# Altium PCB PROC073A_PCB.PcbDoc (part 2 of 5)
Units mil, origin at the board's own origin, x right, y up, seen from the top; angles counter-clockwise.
Board outline 2165.35 x 2165.35 mil, 6 copper layers (Top Layer, L2, L3, L4, L5, Bottom Layer), stack 55.77 mil thick; 284 components, 233 nets, 945 pads, 1419 vias.
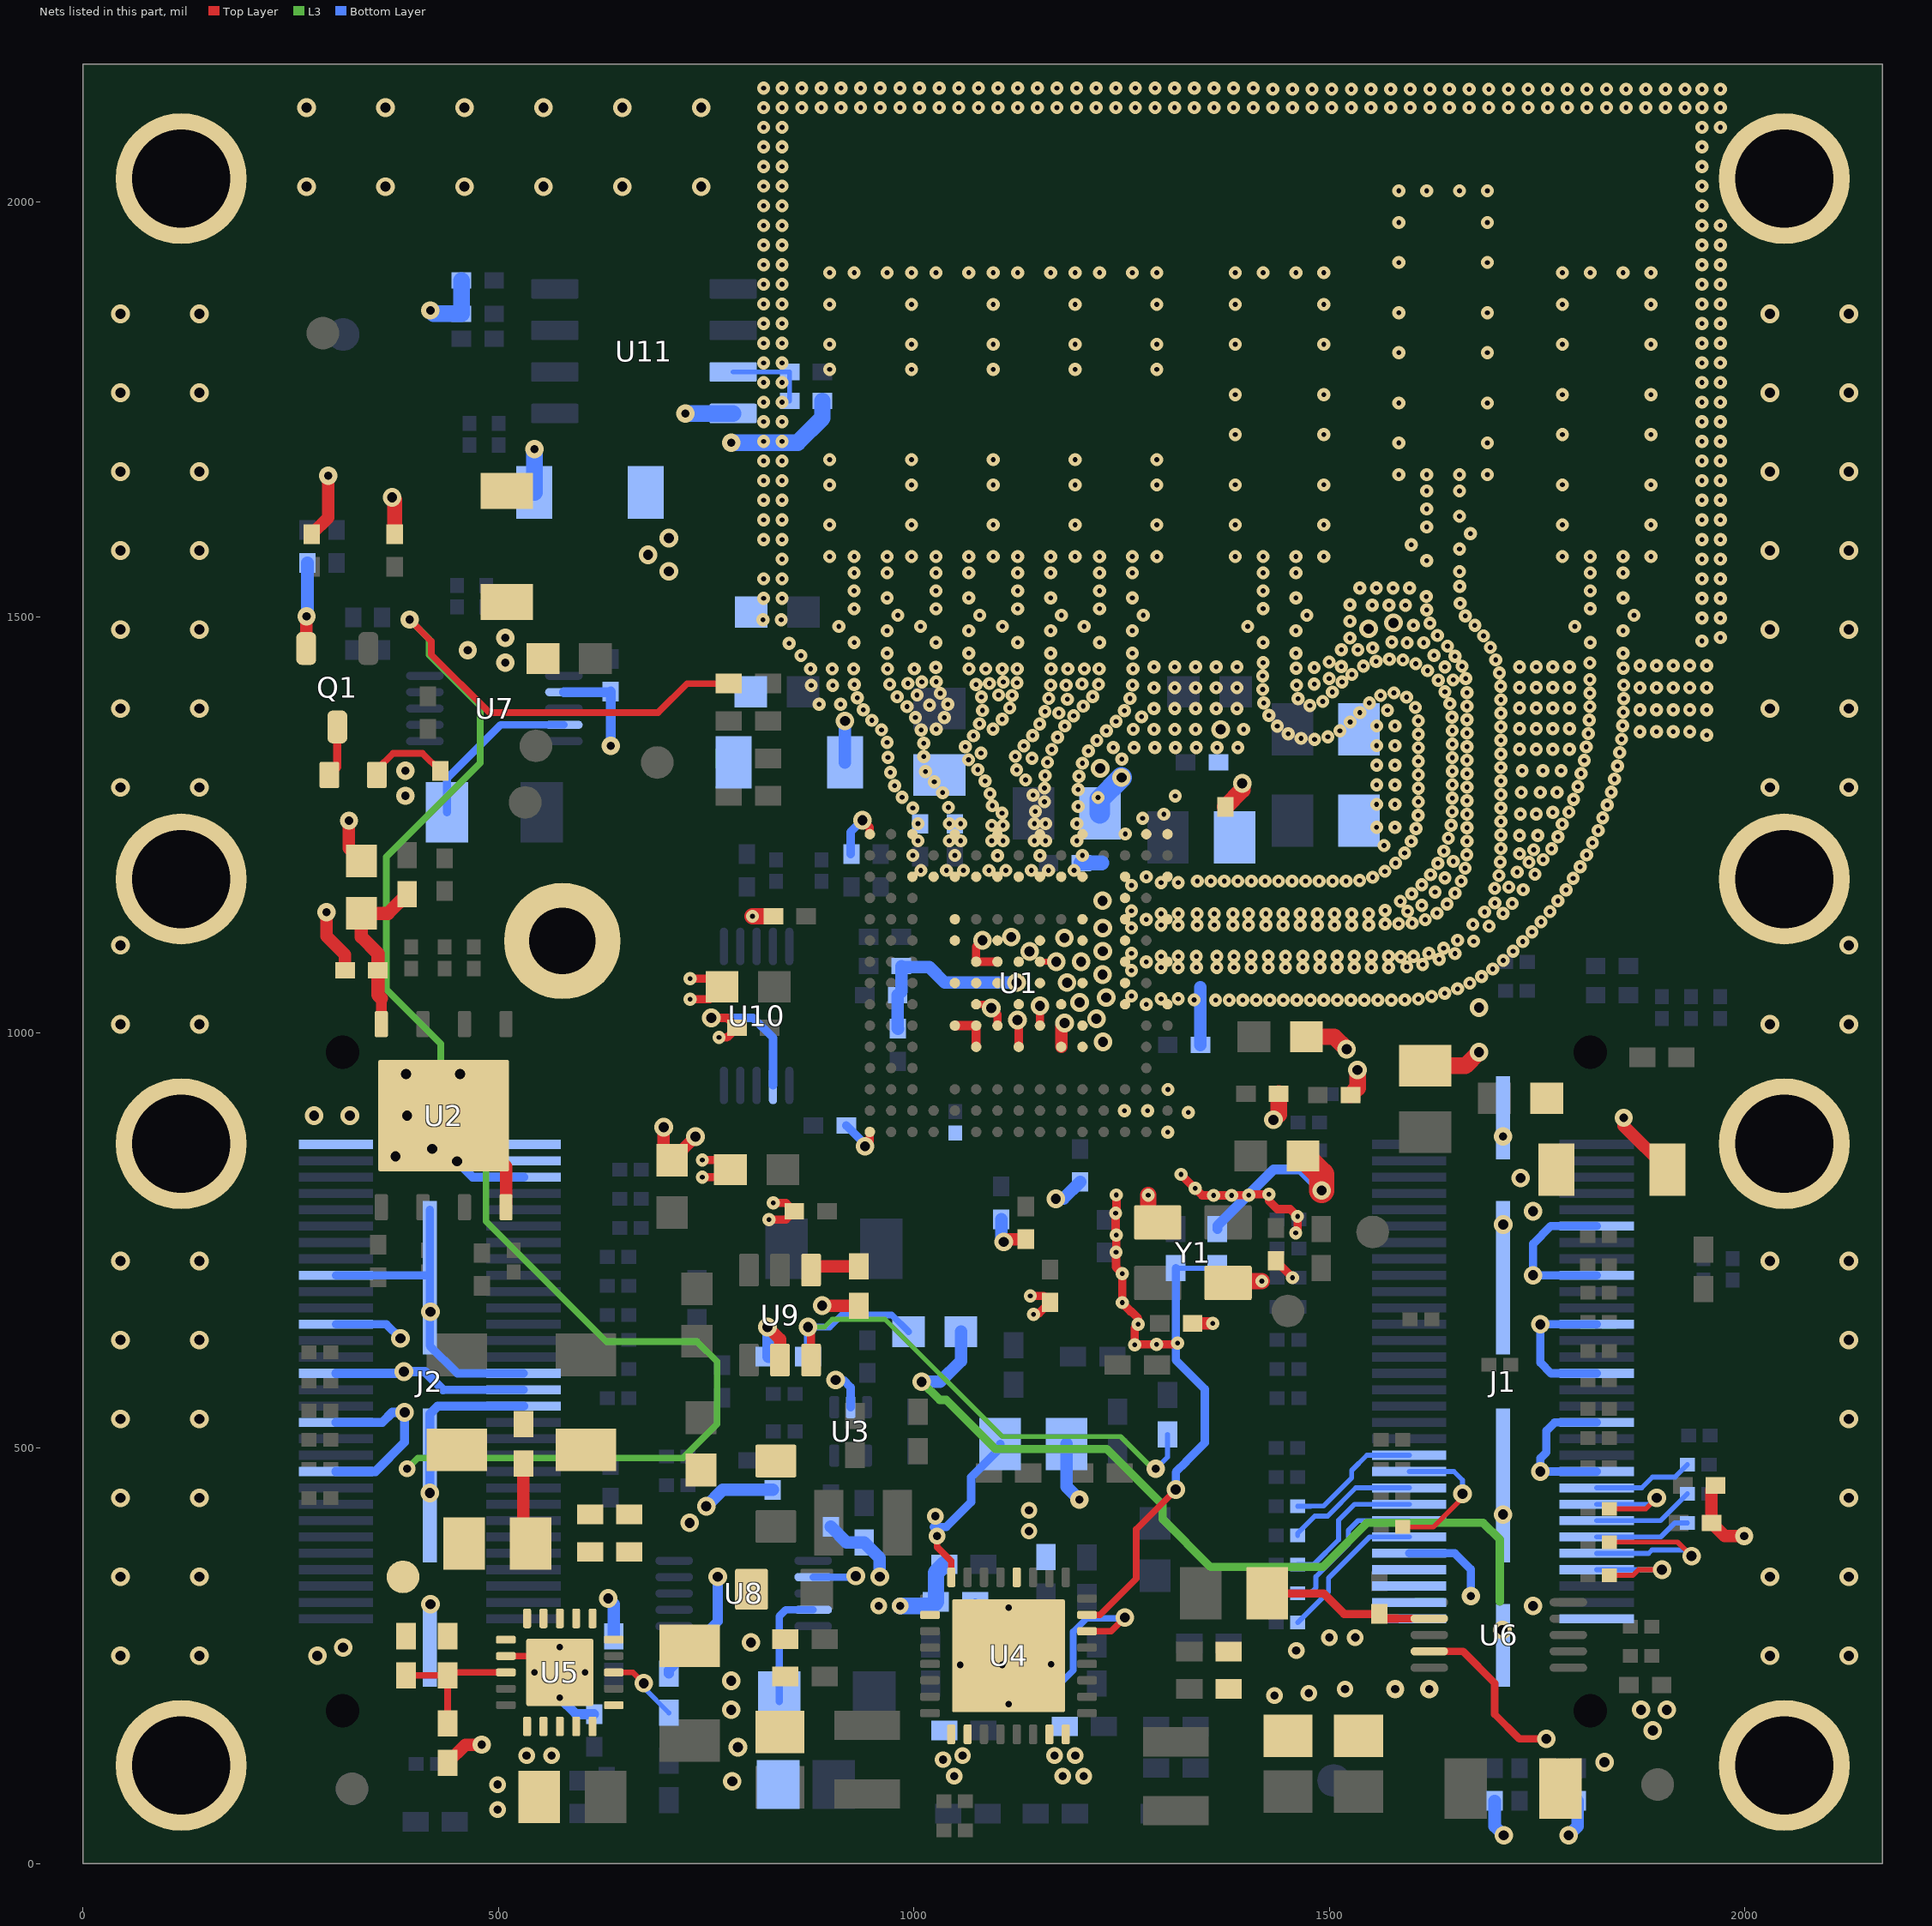
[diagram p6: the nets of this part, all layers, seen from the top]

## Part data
C1 C2 C3 C64: library part CMP-0008770-2, "CAP, CERM, 22 uF, 6.3 V, +/- 10%, X7R, AEC-Q200 Grade 1, 1206", Cap_Case=1206_180, Manufacturer=TDK, Supplier Part Number 1=445-7884-1-ND, TempCo=X7R, Tolerance_%=10%, Value1="0.001872 ohm", Value2=6.3V, ValueDisplayed=22uF
C4 C5 C6 C9 C10 C11 C12 C14 C16 C19 C20 C21 C28 C29: library part CMP-0078265-1, "CAP, CERM, 0.22 µF, 16 V,+/- 10%, X7R, AEC-Q200 Grade 1, 0402", Cap_Case=0402, Manufacturer=MuRata, Supplier Part Number 1=490-10671-1-ND, TempCo=X7R, Tolerance_%=10%, Value2=16V, ValueDisplayed=0.22µF
C7 C8 C13 C15 C23 C24 C45: library part CMP-0008017-2, "CAP, CERM, 10 uF, 10 V, +/- 10%, X7R, 0805", Cap_Case=0805, Manufacturer=MuRata, Supplier Part Number 1=490-10674-1-ND, TempCo=X7R, Tolerance_%=10%, Value1=Unknown, Value2=10V, ValueDisplayed=10uF
C17 C27: library part CMP-0007134-5, "CAP, CERM, 2.2 uF, 6.3 V, +/- 10%, X7R, AEC-Q200 Grade 1, 0603", Cap_Case=0603, Manufacturer=MuRata, Supplier Part Number 1=490-5316-1-ND, TempCo=X7R, Tolerance_%=10%, Value1=Unknown, Value2=6.3V, ValueDisplayed=2.2uF
C18 C22 C35: library part CMP-0007136-5, "CAP, CERM, 1 uF, 16 V, +/- 10%, X7R, AEC-Q200 Grade 1, 0603", Cap_Case=0603, Manufacturer=MuRata, Supplier Part Number 1=490-5241-6-ND, TempCo=X7R, Tolerance_%=10%, Value1=Unknown, Value2=16V, ValueDisplayed=1uF
C25 C26: library part CMP-0006351-2, "CAP, CERM, 0.1 uF, 16 V, +/- 10%, X7R, 0402", Cap_Case=0402, Manufacturer=MuRata, Supplier Part Number 1=490-4759-2-ND, TempCo=X7R, Tolerance_%=10%, Value1=Unknown, Value2=16V, ValueDisplayed=0.1uF
C30: library part CMP-0006352-2, "CAP, CERM, 0.01 uF, 25 V, +/- 10%, X7R, 0402", Cap_Case=0402, Manufacturer=MuRata, Supplier Part Number 1=490-6043-2-ND, TempCo=X7R, Tolerance_%=10%, Value1=Unknown, Value2=25V, ValueDisplayed=0.01uF
C31: library part CMP-0078219-1, "CAP, CERM, 0.1 µF, 10 V,+/- 10%, X7S, 0201", Cap_Case=0201, Manufacturer=TDK, Supplier Part Number 1=445-9051-1-ND, TempCo=X7S, Tolerance_%=10%, Value2=10V, ValueDisplayed=0.1µF
C32 C33: library part CMP-0006367-2, "CAP, CERM, 4.7 pF, 50 V, +/- 2%, C0G/NP0, 0402", Cap_Case=0402, Manufacturer=MuRata, Supplier Part Number 1=490-8102-1-ND, TempCo=C0G/NP0, Tolerance_%=2%, Value1=Unknown, Value2=50V, ValueDisplayed=4.7pF
C34 C36 C57 C58 C59 C63 C65: library part CMP-0006325-2, "CAP, CERM, 0.1 uF, 50 V, +/- 10%, X7R, AEC-Q200 Grade 1, 0402", Cap_Case=0402, Manufacturer=TDK, Supplier Part Number 1=445-6899-1-ND, TempCo=X7R, Tolerance_%=10%, Value1="0.039064 ohm", Value2=50V, ValueDisplayed=0.1uF
C37 C42 C49: library part CMP-0007995-2, "CAP, CERM, 10 uF, 16 V, +/- 10%, X7R, 0805", Cap_Case=0805, Manufacturer="Samsung Electro-Mechanics", TempCo=X7R, Tolerance_%=10%, Value1=Unknown, Value2=16V, ValueDisplayed=10uF
C38 C39 C43 C53 C62 C66 C67: library part CMP-0006201-2, "CAP, CERM, 0.1 uF, 16 V, +/- 10%, X7R, 0402", Cap_Case=0402, Manufacturer=AVX, Supplier Part Number 1=478-7888-1-ND, TempCo=X7R, Tolerance_%=10%, Value1=Unknown, Value2=16V, ValueDisplayed=0.1uF
C40 C41 C44 C46 C47: library part CMP-0008015-1, "CAP, CERM, 22 uF, 6.3 V, +/- 20%, X7T, AEC-Q200 Grade 1, 0805", Cap_Case=0805, Manufacturer=MuRata, TempCo=X7T, Tolerance_%=20%, Value1=Unknown, Value2=6.3V, ValueDisplayed=22uF
C48 C52: library part CMP-0006639-2, "CAP, CERM, 0.01 uF, 16 V, +/- 10%, X7R, 0402", Cap_Case=0402, Manufacturer=MuRata, Supplier Part Number 1=490-1313-1-ND, TempCo=X7R, Tolerance_%=10%, Value1=Unknown, Value2=16V, ValueDisplayed=0.01uF
C50: library part CMP-0007111-4, "CAP, CERM, 1 uF, 6.3 V, +/- 10%, X7R, 0603", Cap_Case=0603, Manufacturer="Samsung Electro-Mechanics", TempCo=X7R, Tolerance_%=10%, Value1=Unknown, Value2=6.3V, ValueDisplayed=1uF
C51: library part CMP-0007359-4, "CAP, CERM, 0.1 uF, 6.3 V, +/- 10%, X7R, 0603", Cap_Case=0603, Manufacturer=MuRata, Supplier Part Number 1=GRM188R70J104KA01D-ND, TempCo=X7R, Tolerance_%=10%, Value1=Unknown, Value2=6.3V, ValueDisplayed=0.1uF
C54 C55 C56: library part CMP-0081763-1, "CAP, CERM, 1 µF, 6.3 V,+/- 10%, X6S, 0402", Cap_Case=0402, Manufacturer=TDK, Supplier Part Number 1=445-13189-1-ND, TempCo=X6S, Tolerance_%=10%, Value2=6.3V, ValueDisplayed=1µF
C60: library part CMP-0006332-2, "CAP, CERM, 1000 pF, 100 V, +/- 10%, X7S, AEC-Q200 Grade 1, 0402", Cap_Case=0402, Manufacturer=TDK, Supplier Part Number 1=445-6904-1-ND, TempCo=X7S, Tolerance_%=10%, Value1="2.71151 ohm", Value2=100V, ValueDisplayed=1000pF
C61: library part CMP-0008203-2, "CAP, CERM, 22 uF, 16 V, +/- 20%, X5R, 0805", Cap_Case=0805, Manufacturer=MuRata, Supplier Part Number 1=490-9952-1-ND, TempCo=X5R, Tolerance_%=20%, Value1=Unknown, Value2=16V, ValueDisplayed=22uF
"CAUTION HOT SURFACE1": library part CMP-0074837-1, "IEC 61010-1 Hot Surface Warning"
DS1: library part CMP-0078196-1, "LED, Yellow, SMD", Color=yellow, Manufacturer=Vishay-Semiconductor, Power_TotalModule=40mW, Supplier Part Number 1=TLMY1000-GS08CT-ND, Value1=.04W, Value2=1.8V
FID1 FID2 FID3 FID4 FID5 FID6: library part CMP-0077181-1, "Fiducial mark.  There is nothing to buy or mount.", Manufacturer=N/A
J1 J2: library part CMP-0075524-1, "Receptacle, 0.5 mm, 30x2, Gold, TH", Color=Black, Manufacturer=Samtec, Supplier Part Number 1=SAM8180-ND
L1 L2 L3 L7: library part CMP-0077879-2, "Ferrite Bead, 120 ohm @ 100 MHz, 1.9 A, 0603", Manufacturer=MuRata, Supplier Part Number 1=490-13261-1-ND, Value1="0.04 ohm", Value2=1.9A, ValueDisplayed="120 ohm"
L4 L5: library part CMP-0058944-1, "Inductor, Shielded, 470 nH, 4.7 A, 0.021 ohm, SMD", Manufacturer="MuRata Toko", Value1="0.021 ohm", Value2=4.7A, ValueDisplayed=470nH
L6: library part CMP-0058938-1, "Inductor, Shielded, 1 uH, 3.8 A, 0.035 ohm, AEC-Q200 Grade 1, SMD", Manufacturer="MuRata Toko", Value1="0.035 ohm", Value2=3.8A, ValueDisplayed=1uH
LBL1: library part CMP-0003625-1, "Thermal Transfer Printable Labels, 0.650\" W x 0.200\" H - 10,000 per roll", Manufacturer=Brady, Supplier Part Number 1=97C5133
Logo1 Logo5: library part CMP-0074838-1, "Texas Instrument Corporate Signature"
Logo2: library part CMP-0074844-1
LOGO3: library part CMP-0074847-1, "FCC_disclaimer"
Logo4: library part CMP-0074769-1
Q1: library part CMP-0000947-2, "MOSFET, N-CH, 100 V, 0.17 A, SOT-23", Alternate Manufacturer=None, Manufacturer="Fairchild Semiconductor", Supplier Part Number 1=BSS123NCT-ND, Value1=1, Value2="1.8 nC"
R1 R99: library part CMP-0025884-3, "RES, 0, 5%, 0.125 W, 0603", Manufacturer=Vishay/Beyschlag, Power_W=125mW, Supplier Part Number 1=MCT0603-0.0-ZZCT-ND, TempCo=ppm/C, Tolerance_%=5%, Value2=0.125W, Value_Code=0000, ValueDisplayed=0
R2 R14 R44 R49 R52 R53 R54 R94 R101 R103 R104 R105 R106 R107 R112 R113 R114 R115 R116 R117 R139 R142 R145 R146 R147 R152 R157 R158 R161 R162: library part CMP-0025958-2, "RES, 10.0 k, 1%, 0.063 W, 0402", Manufacturer=Vishay-Dale, Power_W=63mW, Supplier Part Number 1=541-10.0KLCT-ND, TempCo="100 ppm/C", Tolerance_%=1%, Value2=0.063W, Value_Code=10k0, ValueDisplayed=10.0k
R3 R68 R70 R71 R81 R96 R123: library part CMP-0081623-1, "RES, 0.002, 1%, 1 W, AEC-Q200 Grade 0, 1206", Manufacturer=Rohm, Power_W=1W, Supplier Part Number 1=RHM.002ALCT-ND, TempCo="100 ppm/C", Tolerance_%=1%, Value_Code=2L000, ValueDisplayed=0.002
R4 R5 R6 R7 R8 R9 R10 R11 R12 R13 R16 R22 R24 R30 R31 R32 R33 R34 R35 R36 R37 R38 R39 R40 R41 R42 R58 R59 R60 R61 R62 R63 R64 R65 R66 R67 R131 R133 R134 R135 R136 R137 R140: library part CMP-0027008-3, "RES, 0, 5%, 0.05 W, 0201", Manufacturer=Vishay-Dale, Power_W=50mW, Supplier Part Number 1=72M6743, TempCo=ppm/C, Tolerance_%=5%, Value2=0.05W, Value_Code=0000, ValueDisplayed=0
R15 R17 R18 R19 R20 R21 R23 R26 R27 R28 R124 R125 R126 R127 R128 R129 R130 R132: library part CMP-0078192-1, "RES, 20.0, 1%, 0.05 W, 0201", Manufacturer=Vishay-Dale, Power_W=50mW, Supplier Part Number 1=541-2947-1-ND, TempCo="200 ppm/C", Tolerance_%=1%, Value2=0.05W, Value_Code=20R0, ValueDisplayed=20.0
R25 R29 R55 R56 R88 R89 R108 R109 R110 R111 R143 R144 R149 R159 R160: library part CMP-0027008-4, "RES, 0, 5%, 0.05 W, 0201", Manufacturer=Vishay-Dale, Power_W=50mW, Supplier Part Number 1=72M6743, TempCo=ppm/C, Tolerance_%=5%, Value2=0.05W, Value_Code=0000, ValueDisplayed=0
R43 R72 R73 R74 R75 R76 R77: library part CMP-0026992-3, "RES, 0, 5%, 0.1 W, AEC-Q200 Grade 0, 0402", Manufacturer=Panasonic, Power_W=100mW, Supplier Part Number 1=P0.0JCT-ND, TempCo="600 ppm/C", Tolerance_%=5%, Value2=0.1W, Value_Code=0000, ValueDisplayed=0
R45 R46 R47 R48 R51: library part CMP-0027275-2, "RES, 33.2, 1%, 0.05 W, 0201", Manufacturer=Vishay-Dale, Power_W=50mW, Supplier Part Number 1=541-33.2ABCT-ND, TempCo="200 ppm/C", Tolerance_%=1%, Value2=0.05W, Value_Code=33R2, ValueDisplayed=33.2
R50: library part CMP-0026395-1, "RES, 47.5 k, 1%, 0.063 W, 0402", Manufacturer=Vishay-Dale, Power_W=63mW, Supplier Part Number 1=541-47.5KLCT-ND, TempCo="100 ppm/C", Tolerance_%=1%, Value2=0.063W, Value_Code=47k5, ValueDisplayed=47.5k
R57 R69 R82 R83 R84 R90 R91 R93 R98 R102 R121 R151 R165 R166 R167 R168 R171: library part CMP-0026822-3, "RES, 0, 5%, 0.063 W, AEC-Q200 Grade 0, 0402", Manufacturer=Vishay-Dale, Power_W=63mW, Supplier Part Number 1=541-0.0JCT-ND, TempCo="200 ppm/C", Tolerance_%=5%, Value2=0.063W, Value_Code=0000, ValueDisplayed=0
R78 R79: library part CMP-0078212-1, "RES, 510, 5%, 0.1 W, AEC-Q200 Grade 0, 0402", Manufacturer=Panasonic, Power_W=100mW, Supplier Part Number 1=P510JCT-ND, TempCo="200 ppm/C", Tolerance_%=5%, Value2=0.1W, Value_Code=510R, ValueDisplayed=510
R80 R153 R154 R155 R156: library part CMP-0025950-2, "RES, 100 k, 1%, 0.063 W, 0402", Manufacturer=Vishay-Dale, Power_W=63mW, Supplier Part Number 1=541-100KLCT-ND, TempCo="100 ppm/C", Tolerance_%=1%, Value2=0.063W, Value_Code=100k
R85: library part CMP-0025991-3, "RES, 12.1 k, 1%, 0.063 W, AEC-Q200 Grade 0, 0402", Manufacturer=Vishay-Dale, Power_W=63mW, Supplier Part Number 1=541-12.1KLCT-ND, TempCo="100 ppm/C", Tolerance_%=1%, Value2=0.063W, Value_Code=12k1, ValueDisplayed=12.1k
R86 R87 R95 R100 R118 R141 R148 R150 R163 R164 R169 R170: library part CMP-0026825-5, "RES, 10 k, 5%, 0.063 W, AEC-Q200 Grade 0, 0402", Manufacturer=Vishay-Dale, Power_W=63mW, Supplier Part Number 1=541-10KJCT-ND, TempCo="200 ppm/C", Tolerance_%=5%, Value2=0.063W, Value_Code=10k0, ValueDisplayed=10k
R92: library part CMP-0026399-2, "RES, 48.7 k, 1%, 0.063 W, AEC-Q200 Grade 0, 0402", Manufacturer=Vishay-Dale, Power_W=63mW, Supplier Part Number 1=541-48.7KLCT-ND, TempCo="100 ppm/C", Tolerance_%=1%, Value2=0.063W, Value_Code=48k7, ValueDisplayed=48.7k
R97: library part CMP-0025978-3, "RES, 11.8 k, 1%, 0.063 W, AEC-Q200 Grade 0, 0402", Manufacturer=Vishay-Dale, Power_W=63mW, Supplier Part Number 1=541-11.8KLCT-ND, TempCo="100 ppm/C", Tolerance_%=1%, Value2=0.063W, Value_Code=11k8, ValueDisplayed=11.8k
R119: library part CMP-0026944-3, "RES, 510, 5%, 0.063 W, AEC-Q200 Grade 0, 0402", Manufacturer=Vishay-Dale, Power_W=63mW, Supplier Part Number 1=541-510JCT-ND, TempCo="200 ppm/C", Tolerance_%=5%, Value2=0.063W, Value_Code=510R, ValueDisplayed=510
R120: library part CMP-0026659-1, "RES, 100 k, 1%, 0.1 W, 0402", Manufacturer=Panasonic, Power_W=100mW, TempCo="100 ppm/C", Tolerance_%=1%, Value2=0.1W, Value_Code=100k
R122: library part CMP-0025899-5, "RES, 1.0 k, 5%, 0.1 W, 0603", Manufacturer=Yageo, Power_W=100mW, Supplier Part Number 1=311-1.0KGRCT-ND, TempCo="100 ppm/C", Tolerance_%=5%, Value2=0.1W, Value_Code=1k00, ValueDisplayed=1.0k
R138: library part CMP-0081973-1, "RES, 0, 0%, 0.25 W, AEC-Q200 Grade 0, 0603", Manufacturer=Vishay-Dale, Power_W=250mW, Supplier Part Number 1=541-2779-1-ND, Tolerance_%=0%, Value2=0.25W, Value_Code=0
TP2 TP3 TP4 TP5 TP6 TP7: library part CMP-0003825-1, "1mm Test Point, SMT", Manufacturer=Any
U1: library part CMP-0081105-1, "IWR1843QAGABL, ABL0161B (FCBGA-161)", Alternate Manufacturer="Texas Instruments"
U2: library part CMP-0079267-1, "2.3V-3.6V, 16M-BIT [x 1/x 2/x 4] CMOS FLASH Memory, WSON-8", Manufacturer="Macronix International Co., LTD", Supplier Part Number 1=1092-1211-ND
U3: library part CMP-0067398-2, "Automotive Grade, 1.4V-Capable +/-0.5degC Temperature Sensor with Alert Function and I2C/SMBus, DRL0006A (SOT-OTHER-6)", Alternate Manufacturer="Texas Instruments"
U4: library part CMP-0078631-1, "Boost and Dual Buck Regulators With Diagnostic Functions, RHB0032N (VQFN-32)", Alternate Manufacturer="Texas Instruments"
U5: library part CMP-0077268-2, "Automotive 3A High-Accuracy Low-Noise Low-Dropout (LDO) Voltage Regulator, RGR0020A (VQFN-20)", Manufacturer="Texas Instruments"
U6 U7 U8 U10: library part CMP-0037978-1, "High-Side Measurement, Bi-Directional Current / Power Monitor with I2C Interface, 2.7 to 5.5 V, -40 to 125 degC, 10-pin SOP (DGS10), Green (RoHS & no Sb/Br)", Quiescent Current (+/-)(Typ)(mA)=0.33, Rating=Catalog
U9: library part CMP-0077265-1, "5.5-V, 2-A, 80 mohm Low Leakage Load Switch with RCB and Programmable Rise Time, DBV0006A (SOT-23-6)", Alternate Manufacturer="Texas Instruments", Alternate PartNumber=TPS22917DBVT
U11: library part CMP-0005309-2, "IC, EEPROM, 8KBIT, 400KHZ, 8SOIC", Manufacturer="ON Semiconductor", Supplier Part Number 1=CAT24C08WI-GT3CT-ND
Y1: library part CMP-0004694-3, "Crystal, 40 MHz, 8pF, SMD", Frequency_Fixed=40MHz, Frequency Stability=+/-200ppm, Manufacturer=Kyocera, Supplier Part Number 1=581-CX3225SA40D0PTWC
ZZ1: library part CMP-0003616-3
ZZ2: library part CMP-0077236-1
ZZ3: library part CMP-0077237-1
ZZ4: library part CMP-0077238-1

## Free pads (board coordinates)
  round 157.48 hole 118.11: TH1(118.11,2027.56) TH2(118.11,1184.81) TH3(118.11,866.14) TH4(118.11,118.11) TH5(2047.24,118.11) TH6(2047.24,866.14) TH7(2047.24,1184.81) TH8(2047.24,2027.56)
  round 140 hole 80: TH9(576.76,1110.19)

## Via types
v1: diameter 13.77/15.74 (per signal layer), hole 5.9, Top Layer to L2, tented both sides, 894 vias
v2: diameter 22.4, hole 12.2, Top Layer to Bottom Layer, tented both sides, 340 vias
v3: diameter 13.78/15.75 (per signal layer), hole 5.9, Top Layer to L2, tented both sides, 72 vias
v4: diameter 22, hole 10, Top Layer to Bottom Layer, tented both sides, 54 vias
v5: diameter 20, hole 10, Top Layer to Bottom Layer, tented both sides, 35 vias
v6: diameter 13.77/15.74 (per signal layer), hole 5.9, Top Layer to L2, tented top, 14 vias
v7: diameter 19.68, hole 7.87, Top Layer to Bottom Layer, tented both sides, 9 vias
v8: diameter 13.78/15.75 (per signal layer), hole 5.9, Top Layer to L2, tented top, 1 vias

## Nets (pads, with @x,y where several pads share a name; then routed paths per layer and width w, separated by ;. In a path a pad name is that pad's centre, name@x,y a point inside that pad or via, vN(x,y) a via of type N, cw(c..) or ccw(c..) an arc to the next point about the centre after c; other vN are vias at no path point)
5V_IN: J1.2 J2.1 J2.2 J2.3
  other v2: 1889,160 1875,185 1906,185 282,250 313,260 278,900 321,900
A2: R161.1 R162.2 U11.3 | length 103
  Bottom Layer w6: U11.3@782.28,1795 R161.1@850.32,1795 R162.2@850.31,1760
CB_PMIC_1V0: C2.2 C3.2 J1.1 J1.3 L2.1 L3.1 R71.2 U7.9 | length 208.3
  Bottom Layer w9: 437.91,1305.91 502.31,1370.31 U7.9@578.66,1370.31
  Bottom Layer w10: R71.2@437.91,1265 437.91,1305.91
  other v2: 705,1555 680,1575 705,1595
  other v4: 1579,210 1620,210 388,1285 388,1315
CB_PMIC_1V2: C64.2 J1.5 J1.7 L7.1 R96.2 U8.9 | length 146.5
  Bottom Layer w9: R96.2@837.91,195 837.91,297.57 845.65,305.31 U8.9@878.66,305.31
  other v2: 780,185 780,220
  other v4: 508,1445 463,1460 508,1475
  other v5: 1500,272 1531,272
CB_PMIC_1V8: C1.2 J1.9 L1.1 R70.2 R99.1 U6.9 | length 1317.4
  Top Layer w9: U6.9@1620.08,255.32 1660.68,255.31 1698.74,217.26 1698.74,179.68 1728.42,150 v2(1761,150)
  L3 w10: v2(1009.11,579.71) 1030.9,557.92 1038.78,557.92 1097.92,498.77 1232.16,498.77 1299.2,431.74 1299.2,414.4 1356.81,356.8 1491.8,356.8 1545,410 1685,410 1705,390 1705,315
  Bottom Layer w10: J1.9@1595.95,373.31 1651,373.31 1670,354.31 v4(1670,322)
  Bottom Layer w15: v2(1009.11,579.71) 1031.34,579.71 1056.5,604.87 R99.1@1056.5,640
  other v2: 1831,122 1745,310 1745,785 1730,825
EN_3V3: R69.2 R99.2 R120.2 U9.3 | length 769.1
  Top Layer w10: v2(872.36,645.75) 876.14,641.97 U9.3@876.14,605.87
  L3 w6: v2(872.36,645.75) 892.3,645.75 901.55,655 965.06,655 1106.3,513.76 1248.53,513.76 1287.29,475 v4(1291,475)
  Bottom Layer w6: v4(1291,475) 1305,489 R69.2@1305,516.38
  Bottom Layer w8: v2(872.36,645.75) 898.51,645.75 913.23,660.47 973.04,660.47 ; 961.21,660 972.56,660 973.04,660.47 ; R99.2@993.5,640 973.04,660.47
  Bottom Layer w10: R120.2@872.37,610 v2(872.36,645.75)
GND: C1.1 C2.1 C3.1 C4.1 C5.1 C6.1 C7.1 C8.1 C9.1 C10.1 C11.1 C12.1 C13.1 C14.1 C15.1 C16.1 C17.1 C18.1 C19.1 C20.1 C21.1 C22.1 C23.1 C24.1 C25.1 C26.1 C27.1 C28.1 C29.1 C30.2 C31.1 C32.1 C33.1 C34.1 C35.1 C36.1 C37.1 C38.1 C39.1 C40.1 C41.2 C42.2 C43.1 C44.2 C45.1 C46.2 C47.2 C48.1 C49.2 C50.2 C51.2 C53.1 C54.2 C55.2 C56.2 C57.1 C58.1 C59.1 C60.2 C61.2 C62.1 C63.1 C64.1 C65.1 C66.1 C67.1 J1.20 J1.26 J1.32 J1.38 J1.44 J1.50 J1.MP1 J1.MP2 J1.MP3 J1.MP4 J2.5 J2.18 J2.24 J2.29 J2.30 J2.31 J2.33 J2.36 J2.42 J2.MP1 J2.MP2 J2.MP3 J2.MP4 pad.TH1 pad.TH2 pad.TH3 pad.TH4 pad.TH5 pad.TH6 pad.TH7 pad.TH8 pad.TH9 Q1.2 R57.2 R80.1 R92.1 R97.2 R100.1 R101.1 R103.1 R113.1 R114.1 R116.1 R117.1 R120.1 R146.1 R147.1 R152.1 R155.1 R158.1 R162.1 R164.1 U1.A1 U1.A3 U1.A5 U1.A7 U1.A9 U1.A13 U1.A15 U1.B1 U1.B3 U1.B5 U1.B7 U1.B9 U1.B14 U1.C1 U1.C3 U1.C4 U1.C5 U1.C6 U1.C7 U1.C8 U1.C9 U1.C14 U1.E1 U1.E2 U1.E3 U1.E5 U1.E6 U1.E8 U1.E10 U1.E11 U1.F3 U1.F9 U1.F11 U1.G1 U1.G2 U1.G3 U1.G6 U1.G7 U1.G8 U1.G10 U1.H3 U1.H7 U1.H9 U1.H11 U1.J1 U1.J2 U1.J3 U1.J6 U1.J7 U1.J8 U1.J10 U1.K3 U1.K7 U1.K8 U1.K9 U1.K10 U1.K11 U1.L1 U1.L2 U1.L3 U1.L5 U1.L6 U1.L8 U1.L10 U1.M3 U1.N1 U1.N2 U1.N3 U1.R1 U1.R15 U2.4 U2.9 U3.2 U4.4 U4.10 U4.17 U4.18 U4.23 U4.24 U4.33 U5.2 U5.6 U5.7 U5.8 U5.9 U5.10 U5.11 U5.18 U5.21 U6.7 U7.7 U8.7 U9.2 U10.7 U11.4 Y1.2 Y1.4 | length 6735.5
  Top Layer w7: U1.J7@1100.38,1083.96 U1.J7@1100.39,1085.21 U1.J7@1100.38,1085.68 ; U1.G7@1151.57,1085.21 U1.G7@1151.57,1085.21 v2(1171.17,1085.22)
  Top Layer w8: U5.2@508.78,249.69 U5.21@561.93,249.68
  Top Layer w9: U1.K9@1074.8,1034.03 1088.56,1034.03 v2(1093.07,1029.52) ; 1582,294.69 U6.7@1620.08,294.69
  Top Layer w10: v1(730.59,1040) 754.09,1040 C17.1@769.09,1055 769.09,1055.55 759.39,1065.25 759.14,1065 v1(730.59,1065) ; v1(745.29,825.9) 769.99,825.9 C27.1@779.09,835 767.39,846.7 v1(745.29,846.7) ; v2(756,1017.71) 775.19,1017.71 C21.1@786.91,1006 775,994.09 v1(765.4,994.09) ; v1(825.59,775) 845.9,775 C25.1@855.91,785 845.9,795 v1(830.59,795) ; v2(937.97,1255.62) 946.84,1246.75 U1.R1@946.84,1238.75 ; v2(941.07,863.07) 946.84,868.84 U1.R15@946.84,880.48 ; v2(1082.37,1111.07) 1074.79,1103.49 U1.K7@1074.8,1085.21 U1.J7@1100.39,1085.21 ; v2(1093.07,1029.52) 1100.38,1022.21 U1.J10@1100.39,1008.43 ; v2(1124.47,1015.12) 1125.97,1013.62 U1.H11@1125.98,982.84 ; v1(1139.92,682.96) 1155.94,682.96 C16.1@1163.59,675.32 1150.24,661.96 1144.74,661.96 v1(1143.74,660.96) ; U1.G10@1151.57,1008.43 v2(1151.57,1032.02) ; v1(1243.49,804.5) 1243.59,804.4 1243.59,783.65 v1(1242.66,782.72) 1242.66,757.13 v1(1243.49,756.3) 1243.49,736.1 v1(1243.09,735.7) 1243.09,717.5 v1(1250.59,710) v1(1250.59,675) 1269.74,655.85 v1(1269.74,649) 1265.69,644.95 v1(1265.69,624.22) ; v1@1250.2,674.61 1260.59,664.22 ; v1@1266.29,624.82 v1(1291.99,624.82) v1@1315.69,624.82 ; v1(1321.28,829.43) v1(1338.23,812.48) 1346.73,803.98 v1(1360.63,803.98) v1(1382.33,803.98) 1382.73,804.38 v1(1402.93,804.38) 1403.93,805.38 v1(1427.03,805.38) 1427.03,797.71 1437.24,787.49 1452.71,787.49 v1(1461.53,778.68) 1461.53,761 v1(1459.43,758.9) ; Y1.2@1377.91,698.58 Y1.2@1380.15,700.82 ; C37.1@1425,325 1493,325 1517.68,300.31 C57.1@1560,300.32 1565.63,294.68 1582,294.68 ; C32.1@1435.59,725.32 1435.59,725 v1(1455.59,705)
  Top Layer w11: U1.L10@1049.21,1008.43 U1.K10@1074.8,1008.43 U1.K11@1074.8,982.84
  Top Layer w15: Q1.2@268.6,1462.24 v4@268.6,1501 ; R114.1@275,1599.69 295,1619.68 v4(295,1670) ; v4(293,1145) 293,1116 315.31,1093.68 C34.1@315.32,1075 ; v4(320,1255) 320,1221.49 C35.1@335,1206.5 ; U2.9@434,900 448,900 509,839 U2.4@509,789.76 ; R92.1@438.74,121.38 460.36,143 v4(479.74,143) ; v2(453.74,950) U2.9@456.26,950 ; R164.1@530,481.38 530,403.74 538.74,395 C44.2@538.74,385 ; v2(698.74,886) 698.74,856.5 C51.2@708.74,846.5 v2(736.99,874.75) ; v2(823.74,645.67) 838.74,630.67 U9.2@838.74,605.87 ; v2(889.36,671.38) C60.2@933.74,671.38 ; v2(1108,748) 1111.31,751.31 C26.1@1135.59,751.31 ; U1.F11@1177.16,982.84 1177.15,1007.4 v2(1181.17,1011.42) ; C33.1@1335.28,650 v6(1359.59,650) ; v4(1854,897.5) 1854,887.93 C1.1@1906.93,835 ; R155.1@1964.68,455 1959.68,450 R152.1@1959.68,410 1975.69,394 v4(1999,394)
  Top Layer w18: v2(372,1644) 375,1641 R113.1@375,1599.69
  Top Layer w20: v1(805.59,1140) C28.1@830.91,1140 ; v1(1281.8,804.28) 1281.8,782.88 Y1.4@1293.27,771.42 ; C4.1@1374.59,1271.68 1395,1292.09 v2(1395,1300) ; Y1.2@1380.15,700.82 v1(1418.59,700.82) ; v2(1432.59,895) 1438.87,901.27 C5.1@1438.87,926.41 ; C22.1@1472.09,995 1505.59,995 v2(1520.59,980) ; C14.1@1525.28,925 1533.74,933.46 v2(1533.74,955) ; C15.1@1615,960 1663.54,960 v2(1680,976.46)
  Top Layer w30: C18.1@1468.28,851.41 1490.59,829.09 v2(1490.59,810)
  Bottom Layer w9: U8.7@878.66,344.68 v2@928.68,344.68
  Bottom Layer w10: J2.24@304.44,648.9 365.1,648.9 v2(382,632) ; J2.18@304.44,707.95 414.29,707.95 J2.MP2@417.24,705 ; J2.MP2@417.24,786.69 J2.MP2@417.24,705 ; 433.2,570.16 J2.31@530.04,570.16 ; J2.29@530.04,589.84 450.49,589.84 417.24,623.1 J2.MP2@417.24,705 ; v2(756,1017.71) 806.28,1017.71 830.27,993.72 U10.7@830.28,936.34 ; v2(905.74,582) 914.74,582 923.74,573 U3.2@923.74,549.13 ; C63.1@918.43,888.19 941.07,865.54 v2(941.07,863.07) ; R146.1@923.74,1214.68 923.74,1241.39 v2(937.97,1255.62) ; v2@928.68,344.68 v2(930,346) ; J1.20@1821.54,471.73 v2(1753.74,471.73) 1753.74,487.8 1760.94,495 1760.94,520.94 1770.79,530.79 J1.26@1821.54,530.79 ; J1.32@1821.54,589.84 1766.46,589.84 1753.74,602.56 v2(1753.74,648.9) J1.38@1821.54,648.9 ; J1.44@1821.54,707.95 v2(1745,707.95) 1745,746 1766.01,767.01 J1.50@1821.54,767.01
  Bottom Layer w11: J2.42@304.44,471.73 351.73,471.73 387,507 v2(387,543) 372.21,543 360,530.79 J2.36@304.44,530.79 ; J2.30@304.44,589.84 v2@383.84,589.84 ; v2(386,592) 411.36,592 433.2,570.16 ; J2.MP3@417.24,455 417.24,540.85 426.86,550.47 J2.33@530.04,550.47 ; v2(450,845) 468.93,826.07 J2.5@530.04,826.07
  Bottom Layer w12: v7(573.74,199.49) 593.55,179.68 R117.1@615,179.68 ; U7.7@578.66,1409.68 634.37,1409.68 C58.1@635,1410.32 v4(635,1345) ; C48.1@705,228.62 705,232.56 763.74,291.3 v2(763.74,345) ; C67.1@1365,763.62 1365,767.56 1432.64,835.2 1465.39,835.2 v2(1490.59,810)
  Bottom Layer w15: v4(269,1501) 270,1502 R80.1@270,1565.31 ; v2(750,430) 769.68,449.68 C59.1@830,449.68 ; v2(823.74,645.67) 825.12,644.29 R120.1@825.12,610 ; C36.1@900,405.32 918.94,386.38 R57.2@940,386.38 958.74,367.64 v2(958.74,345) ; C3.1@916.93,1325 v2(916.93,1375) ; C29.1@980.59,1004.68 980.27,1005 C10.1@980.28,1045 984.68,1049.41 R147.1@984.68,1080 985.86,1078.82 1018.39,1078.82 1037.21,1060 1079.88,1060 1080,1060.12 v2(1123.47,1060.12) ; C30.2@1105,775.31 1105,751 v2(1108,748) ; v2(1170.59,800) 1179.68,800 C9.1@1200,820.32 ; C61.2@1183.74,505 1183.74,453.26 v4(1199,438) ; C6.1@1344.68,985 1344.68,1054.68 ; v2(1490.59,810) v2@1490.59,810.08 ; R101.1@1698.74,75.32 1698.74,45 v2(1709.74,34) ; v2(1787.74,34) 1798.74,45 R103.1@1798.74,75.32
  Bottom Layer w18: C12.1@1201.28,1204 1226,1204
  Bottom Layer w20: v4(418,1869) 422,1865 R158.1@455.32,1865 C65.1@455.32,1905 ; C2.1@543.07,1650 v4(543.07,1702.07) ; v4(725,1745) U11.4@782.28,1745 ; v4(780,1710) 860,1710 889.68,1739.68 R162.1@889.68,1760 ; v5(983.43,310) 1021.38,310 C66.1@1026.38,315 1026.38,350 C62.1@1036.38,360
  Bottom Layer w25: C13.1@1223.59,1264 1223.59,1280.85 v2(1249.69,1306.95)
  other v1: 1317.09,626.22 1305.31,880.28 1330,904 1253.08,905.86 1281.08,905.86 1305.58,931.45 1279.52,1034.02 1337.05,1039.41 1362.97,1039.01 1379.24,1039.01 1395.5,1039.01 1411.77,1039.01 1428.03,1039.01 1444.3,1039.01 1460.56,1039.01 1476.83,1039.01 1493.09,1039.01 1509.36,1039.01 1525.62,1039.01 1541.89,1039.01 1558.15,1039.01 1574.42,1039.01 1590.68,1039.38 1606.91,1040.44 1297.24,1040.63 1317.9,1040.63 1622.9,1043.42 1261.81,1044.05 1638.67,1047.4 1654.07,1052.62 1668.78,1059.57 1683.02,1067.42 1261.81,1074.76 1696.54,1076.46 1297.24,1078.18 1317.9,1078.18 1279.52,1085 1709,1086.91 1297.23,1091.81 1317.89,1091.81 1261.8,1095.23 1720.95,1097.94 1732.45,1109.45 1673.43,1109.91 1743.69,1121.21 1261.8,1125.94 1297.23,1129.36 1317.89,1129.36 1566.95,1130.99 1583.22,1130.99 1599.46,1131.78 1754.61,1133.26 1279.51,1136.18 1615.23,1135.79 1297.23,1142.99 1317.89,1142.99 1547,1143 1708.91,1143.38 1629.44,1143.68 1261.8,1146.41 1765.24,1145.57 1567,1147 1641.4,1154.71 1719.83,1155.43 1585.34,1157.98 1774.93,1158.63 1598.86,1167.02 1651.14,1167.74 1784.62,1171.7 1698.87,1173.46 1715.74,1175 1261.8,1177.12 1611.09,1177.75 1297.23,1180.54 1317.89,1180.54 1341,1182.17 1357.27,1182.17 1373.53,1182.17 1389.8,1182.17 1406.06,1182.17 1422.33,1182.17 1438.59,1182.17 1454.86,1182.17 1471.12,1182.17 1487.39,1182.17 1503.65,1182.17 1519.92,1182.17 1658.5,1182.24 1536.15,1183.07 1793.23,1185.5 1279.51,1187.36 1551.94,1186.98 1621.65,1190.11 1725.74,1193 1566.61,1194.01 1008.26,1195.24 1038.97,1195.24 1059.44,1195.24 1090.15,1195.24 1110.62,1195.24 1141.33,1195.24 1161.8,1195.24 1192.51,1195.24 1663.26,1197.79 1801.59,1199.45 1579.54,1203.87 1630.47,1203.78 1705.38,1205.28 1740,1205 1049.21,1213.16 1100.39,1212.95 1151.57,1212.95 1202.75,1213.16 1665.28,1213.93 1809.41,1213.71 1728.74,1215.16 1590.31,1216.06 1637.61,1218.39 1745.74,1220 1767.26,1221.25 1706.22,1221.52 1565.74,1225 1816.36,1228.41 1598.46,1230.13 1665.42,1230.2 1004.84,1230.67 1042.39,1230.67 1056.02,1230.67 1093.57,1230.67 1107.2,1230.67 1144.75,1230.67 1158.38,1230.67 1195.93,1230.67 1642.96,1233.76 1774.81,1235.65 1728.74,1237.16 1750.74,1237.16 1706.22,1237.79 1254.13,1238.96 1823.27,1243.14 1603.95,1245.45 1665.42,1246.46 1556.74,1246.95 1578.9,1246.95 1093.57,1249.33 1107.2,1249.33 1646.44,1249.64 1004.84,1251.33 1042.39,1251.33 1056.02,1251.33 1144.75,1251.33 1158.38,1251.33 1195.93,1251.33 1706.22,1254.05 1275.08,1257.86 1828.85,1258.42 1606.59,1261.49 1300.58,1262.86 1665.42,1262.72 1729.74,1263.11 1748.74,1263.11 1106,1264 1768.74,1265 1788.14,1265.32 1146.02,1266.08 1647.72,1265.86 998.62,1270.16 1706.22,1270.32 1041.46,1270.94 1197.56,1272.1 1094.35,1273 1834.33,1273.73 1556.74,1274.51 1578.9,1274.51 1157.08,1277.72 1607,1277.75 1665.42,1278.99 1793.62,1280.64 1647.79,1282.12 985.62,1283.16 1221.58,1282.86 1314.28,1284.76 1143.22,1285.79 1706.22,1286.58 1091.55,1287.56 1034.33,1288.68 1730.74,1289.05 1753.74,1289.05 1773.74,1289.05 1838.99,1289.31 1197.56,1292.3 1157.08,1294.26 1607,1294.02 1665.42,1295.25 1798.77,1296.06 976.62,1297.16 1556.74,1298.13 1578.9,1298.13 1647.79,1298.39 1024.45,1301.6 1085.58,1302.69 1706.22,1302.85 1134.21,1303.99 1842.94,1305.09 1157.74,1309.13 1198.59,1308.53 1607,1310.28 1665.42,1311.52 1802.72,1311.84 971.62,1313.16 1013.89,1313.97 1647.79,1314.65 1731.74,1315 1756.74,1315 1778.74,1315 1076.69,1316.31 1123.56,1316.28 1706.22,1319.11 1846.71,1320.91 1556.74,1321.75 1578.9,1321.75 1202.74,1324.26 1160.66,1325.13 1607,1326.55 1065.72,1328.32 1665.42,1327.78 1806.61,1327.63 1250,1329 1141.94,1329.98 968.62,1331.16 1647.79,1330.92 1011.62,1332.16 1121.92,1332.46 1706.22,1335.38 1080.65,1336.35 1849.1,1337 1209.99,1338.82 1165.66,1340.61 1728.74,1340.94 1748.74,1340.94 1768.74,1340.94 1788.74,1340.94 1239.74,1343 1264.74,1343 1289.74,1343 1314.74,1343 1339.74,1343 1364.74,1343 1389.74,1343 1607,1342.81 1061.86,1344.12 1665.42,1344.05 1809,1343.72 1132.26,1345.02 1556.74,1345.38 1578.9,1345.38 1647.79,1347.18 1011.62,1348.16 967.62,1349.16 1220.05,1351.6 1706.22,1351.64 1481.97,1352.87 1851.49,1353.09 1465.75,1354.06 1172.66,1355.29 1497.93,1355.97 1071.51,1357.21 1142.67,1357.52 1953.98,1358.05 1607,1359.08 1450.42,1359.51 1665.42,1360.31 1811.38,1359.81 1873.55,1361.99 1893.53,1361.99 1913.54,1361.99 1933.52,1361.99 1231.62,1363.03 1512.53,1363.13 1647.79,1363.44 960.84,1364.28 1008.62,1364.16 1026.62,1365.16 1095.15,1365.12 1263.74,1365 1288.74,1365 1313.74,1365 1338.74,1365 1396.74,1365 1728.74,1365.71 1748.74,1365.71 1768.74,1365.71 1788.74,1365.71 1706.22,1367.9 1181.53,1368.92 1437.1,1368.84 1556.74,1369 1578.9,1369 1852.78,1369.3 1151.18,1371.38 1078.92,1371.69 1243.21,1374.44 1524.97,1373.62 1607,1375.34 949.34,1375.78 1812.41,1376.04 1106.16,1377.09 1665.42,1376.58 1001.62,1379.16 1036.62,1379.16 1273.74,1380 1647.44,1379.71 1192.14,1381.25 1427.08,1381.65 1706.22,1384.17 1174.3,1384.63 1536.47,1385.12 1157.62,1386.31 1853.58,1385.55 1253.2,1387.27 938.95,1388.3 1082.34,1387.59 1569.74,1388 1873.55,1388.49 1893.53,1388.49 1913.54,1388.49 1933.52,1388.49 1953.98,1388.49 1288.74,1390 1313.74,1390 1338.74,1390 1363.74,1390 1388.74,1390 1728.74,1390.47 1748.74,1390.47 1768.74,1390.47 1788.74,1390.47 1115.1,1390.68 1603.27,1391.17 991.62,1392.16 1813.21,1392.29 1203.64,1392.75 1665.42,1392.84 1018.62,1394.16 1476.3,1393.68 885.86,1395.16 911.74,1395.16 1040.62,1395.16 1644.78,1395.75 1420.97,1396.72 1547.97,1396.62 1491.83,1398.49 1706.22,1400.43 1184.62,1401.16 1162.03,1401.97 1259.92,1402.09 1462.28,1401.92 1854.01,1401.8 931.71,1402.86 979.62,1404.16 1081.18,1403.81 1215.08,1404.31 1592.84,1403.65 1003.62,1406.16 1101.66,1406.16 1561.49,1405.66 1031.62,1408.16 1577.44,1408.88 1665.42,1409.11 1813.21,1408.55 1503.49,1409.83 1419.51,1412.92 1288.74,1415 1313.74,1415 1338.74,1415 1363.74,1415 1388.74,1415 1728.74,1415.23 1748.74,1415.23 1768.74,1415.23 1788.74,1415.23 1873.55,1415 1893.53,1415 1913.54,1415 1933.52,1415 1953.98,1415 1706.05,1416.7 876.32,1417.88 902.2,1417.88 1164.35,1418.07 1263,1418.06 1460.31,1418.07 1854.01,1418.07 928.08,1418.71 970.62,1419.16 1074.71,1418.74 1222.11,1418.98 1481.65,1419.26 992.62,1420.16 1090.66,1420.16 1202.2,1419.57 1009.47,1421.87 1026.62,1422.16 1107.51,1421.87 1515,1422 1648.83,1424.38 1813.21,1424.82 1499.62,1425.94 1419.51,1429.19 1527,1431 1704.44,1432.88 1617.97,1435.62 875.62,1437.57 901.49,1437.57 927.37,1437.57 968.17,1437.57 1000.3,1437.57 1066.23,1437.57 1086.21,1437.56 1106.22,1437.57 1124.23,1437.57 1165.03,1437.57 1185,1437.56 1205.02,1437.57 1222.65,1437.57 1263.45,1437.57 1459.84,1438.49 1853.54,1438.49 1481.64,1439.27 1288.74,1440 1313.74,1440 1338.74,1440 1363.74,1440 1388.74,1440 1638.99,1440.01 1728.74,1440 1748.74,1440 1768.74,1440 1788.74,1440 1514.23,1440.55 1540.83,1440.92 1659.55,1440.88 1893.53,1441.49 1933.52,1441.49 1953.98,1441.49 1873.55,1441.5 1913.54,1441.5 1603.91,1443.79 1420.03,1445.25 1813.21,1444.82 1499.61,1445.95 1556.03,1446.7 1588.33,1448.45 1572.08,1449.3 1700.01,1448.53 863.94,1453.78 1625.84,1454.02 967.55,1456.46 1065.98,1456.46 1164.41,1456.46 1262.84,1456.46 1459.7,1456.48 1853.4,1456.48 1514.22,1460.56 1534.23,1460.57 1552,1463 1693.57,1463.47 849.84,1468.46 1593.39,1469.17 1613.4,1469.18 1575,1470 1948.27,1471.31 1524.57,1474.91 1970.43,1475.25 1685.24,1477.43 967.55,1483.49 1065.98,1483.49 1164.41,1483.49 1262.84,1483.49 1459.69,1483.5 1853.39,1483.5 909.5,1488.7 1007.93,1488.7 1106.36,1488.7 1204.79,1488.7 1401.65,1488.71 1795.35,1488.71 1601,1490 1674.91,1490 1620.8,1492.71 1524.56,1494.92 818.11,1496.65 840.27,1496.65 1948.27,1498.87 1970.43,1498.87 1663.37,1501.46 980.54,1502.08 1078.97,1502.08 1177.4,1502.08 1275.83,1502.08 1472.69,1502.09 1866.39,1502.09 1616.87,1508.49 928,1510.03 1026.43,1510.03 1124.86,1510.03 1223.29,1510.03 1420.15,1510.05 1813.85,1510.05 1551.47,1514.33 1571.48,1514.34 1591.46,1514.33 1524.57,1514.9 1657.16,1516.49 819.09,1522.48 841.26,1522.48 1948.27,1522.49 1970.43,1522.49 967.56,1523.03 1065.99,1523.03 1164.42,1523.03 1262.85,1523.03 1459.69,1523.05 1853.39,1523.05 1616.36,1524.75 927.99,1531.66 1026.42,1531.66 1124.85,1531.66 1223.28,1531.66 1420.14,1531.67 1813.84,1531.67 1536.37,1534.91 1556.35,1534.9 1576.36,1534.91 1596.34,1534.9 1656.69,1536.92 819.09,1546.1 841.26,1546.1 1948.27,1546.12 1970.43,1546.12 928,1553.26 967.55,1553.26 1026.43,1553.26 1065.98,1553.26 1124.86,1553.26 1164.41,1553.26 1223.29,1553.26 1262.84,1553.26 1420.15,1553.28 1459.69,1553.28 1813.85,1553.28 1853.39,1553.28 1656.55,1554.9 841.26,1569.72 1948.27,1569.74 1970.43,1569.74 898.55,1572.95 928,1572.95 967.55,1572.95 997,1572.95 1026.43,1572.95 1065.98,1572.95 1095.43,1572.95 1124.86,1572.95 1164.41,1572.95 1193.86,1572.95 1223.29,1572.95 1262.84,1572.95 1292.29,1572.95 1386.65,1572.96 1420.15,1572.96 1459.69,1572.96 1493.18,1572.96 1780.35,1572.96 1813.85,1572.96 1853.39,1572.96 1886.88,1572.96 1656.54,1581.93 1598.5,1587.13 819.09,1593.34 841.26,1593.34 1948.27,1593.36 1970.43,1593.36 1669.54,1600.52 1617,1608.48 898.55,1611.1 996.98,1611.12 1095.41,1611.12 1193.84,1611.12 1292.27,1611.12 1386.65,1611.11 1493.18,1611.11 1780.35,1611.11 1886.88,1611.11 819.09,1616.97 841.26,1616.97 1948.27,1616.98 1970.43,1616.98 1656.54,1621.47 1616.99,1630.1 819.09,1640.59 841.26,1640.59 1948.27,1640.6 1970.43,1640.6 1617,1651.7 1656.54,1651.7 898.55,1659.13 996.97,1659.13 1095.4,1659.13 1193.83,1659.13 1292.26,1659.13 1386.65,1659.14 1493.18,1659.14 1780.35,1659.14 1886.88,1659.14 819.09,1664.21 841.26,1664.21 1948.27,1664.23 1970.43,1664.23 1583.5,1671.39 1617,1671.39 1656.54,1671.39 1690.03,1671.39 819.09,1687.83 841.26,1687.83 1948.27,1687.85 1970.43,1687.85 898.55,1689.4 996.97,1689.4 1095.4,1689.4 1193.83,1689.4 1292.26,1689.4 1583.5,1709.53 1690.03,1709.53 819.09,1711.45 841.26,1711.45 1948.27,1711.47 1970.43,1711.47 1386.65,1719.69 1493.18,1719.69 1780.35,1719.69 1886.88,1719.69 819.09,1735.08 841.26,1735.08 1948.27,1735.09 1970.43,1735.09 1583.5,1757.57 1690.03,1757.57 819.09,1758.7 841.26,1758.7 1948.27,1758.71 1970.43,1758.71 1386.65,1767.72 1493.18,1767.72 1780.35,1767.72 1886.88,1767.72 819.09,1782.32 841.26,1782.32 1948.27,1782.34 1970.43,1782.34 898.55,1797.99 996.97,1797.99 1095.4,1797.99 1193.83,1797.99 1292.26,1797.99 819.09,1805.94 841.26,1805.94 1948.27,1805.96 1970.43,1805.96 1583.5,1818.12 1690.03,1818.12 898.55,1828.26 996.97,1828.26 1095.4,1828.26 1193.83,1828.26 1292.26,1828.26 1386.65,1828.28 1493.18,1828.28 1780.35,1828.28 1886.88,1828.28 819.09,1829.57 841.26,1829.57 1948.27,1829.58 1970.43,1829.58 819.09,1853.19 841.26,1853.19 1948.27,1853.2 1970.43,1853.2 1583.5,1866.15 1690.03,1866.15 898.55,1876.29 996.97,1876.29 1095.4,1876.29 1193.83,1876.29 1292.26,1876.29 1386.65,1876.31 1493.2,1876.31 1780.35,1876.31 1886.9,1876.31 819.09,1876.81 841.26,1876.81 1948.27,1876.82 1970.43,1876.82 819.09,1900.43 841.26,1900.43 1948.27,1900.45 1970.43,1900.45 898.55,1914.44 928,1914.44 967.56,1914.44 996.97,1914.44 1026.43,1914.44 1065.99,1914.44 1095.4,1914.44 1124.86,1914.44 1164.42,1914.44 1193.83,1914.44 1223.29,1914.44 1262.85,1914.44 1292.26,1914.44 1386.65,1914.46 1420.15,1914.46 1459.69,1914.46 1493.2,1914.46 1780.35,1914.46 1813.85,1914.46 1853.39,1914.46 1886.9,1914.46 819.09,1924.05 841.26,1924.05 1948.27,1924.07 1970.43,1924.07 1583.5,1926.7 1690.03,1926.7 819.09,1947.68 841.26,1947.68 1948.27,1947.69 1970.43,1947.69 819.09,1971.3 841.26,1971.3 1948.27,1971.31 1970.43,1971.31 1583.5,1974.73 1690.05,1974.73 819.09,1994.92 841.26,1994.92 1948.27,1994.93 1583.5,2012.88 1617,2012.88 1656.54,2012.88 1690.05,2012.88 819.09,2018.54 841.26,2018.54 1948.27,2018.56 819.09,2042.16 841.26,2042.16 1948.27,2042.18 819.09,2065.79 841.26,2065.79 1948.27,2065.8 819.09,2089.41 841.26,2089.41 1948.27,2089.42 1970.43,2089.42 819.09,2113.03 841.26,2113.03 864.88,2113.03 888.5,2113.03 912.13,2113.03 935.75,2113.03 959.37,2113.03 982.99,2113.03 1006.61,2113.03 1030.24,2113.03 1053.86,2113.03 1077.48,2113.03 1101.1,2113.03 1124.72,2113.03 1148.35,2113.03 1171.97,2113.03 1195.59,2113.03 1219.21,2113.03 1242.83,2113.03 1266.46,2113.03 1290.08,2113.03 1313.7,2113.03 1337.32,2113.03 1360.94,2113.03 1384.57,2113.03 1408.19,2113.03 1431.81,2113.03 1455.43,2113.03 1479.05,2113.03 1502.68,2113.03 1526.3,2113.03 1549.92,2113.03 1573.54,2113.03 1597.16,2113.03 1620.79,2113.03 1644.41,2113.03 1668.03,2113.03 1691.65,2113.03 1715.27,2113.03 1738.9,2113.03 1762.52,2113.03 1786.14,2113.03 1809.76,2113.03 1833.38,2113.03 1857.01,2113.03 1880.63,2113.03 1904.25,2113.03 1927.87,2113.03 1948.27,2113.03 1970.43,2113.03 1431.81,2135.19 1455.43,2135.19 1479.05,2135.19 1502.68,2135.19 1526.3,2135.19 1549.92,2135.19 1573.54,2135.19 1597.16,2135.19 1620.79,2135.19 1644.41,2135.19 1668.03,2135.19 1691.65,2135.19 1715.27,2135.19 1738.9,2135.19 1762.52,2135.19 1786.14,2135.19 1809.76,2135.19 1833.38,2135.19 1857.01,2135.19 1880.63,2135.19 1904.25,2135.19 1927.87,2135.19 1948.27,2135.19 1970.43,2135.19 819.09,2136.65 841.26,2136.65 864.88,2136.65 888.5,2136.65 912.13,2136.65 935.75,2136.65 959.37,2136.65 982.99,2136.65 1006.61,2136.65 1030.24,2136.65 1053.86,2136.65 1077.48,2136.65 1101.1,2136.65 1124.72,2136.65 1148.35,2136.65 1171.97,2136.65 1195.59,2136.65 1219.21,2136.65 1242.83,2136.65 1266.46,2136.65 1290.08,2136.65 1313.7,2136.65 1337.32,2136.65 1360.94,2136.65 1384.57,2136.65 1408.19,2136.65
  other v2: 781.21,98.96 788,140 45,250 140,250 2030,250 2125,250 803.74,266 1708,281 418,312 45,345 140,345 2030,345 2125,345 730,410 1708.74,420 45,440 140,440 2125,440 417.24,446 45,535 140,535 2125,535 45,630 140,630 2125,630 418,664 45,725 140,725 2030,725 2125,725 1709,769 376,851 420,860 390,900 388.74,950 1227.47,988.87 45,1010 140,1010 2030,1010 2125,1010 1219.57,1016.67 1680,1030 1199.37,1036.27 1231.37,1042.17 1184.17,1060.12 1226.87,1069.82 1201.17,1085.22 1139.07,1097.67 1227.07,1097.82 45,1105 2125,1105 1180.97,1113.82 1117.07,1115 1227.07,1125.82 1226.87,1158.67 45,1295 140,1295 2030,1295 2125,1295 1224,1318 1369.04,1364.8 45,1390 140,1390 2030,1390 2125,1390 45,1485 140,1485 2030,1485 2125,1485 1547,1486 1577,1493 45,1580 140,1580 2030,1580 2125,1580 45,1675 140,1675 2030,1675 2125,1675 45,1770 140,1770 2030,1770 2125,1770 45,1865 140,1865 2030,1865 2125,1865 269,2018 364,2018 459,2018 554,2018 649,2018 744,2018 269,2113 364,2113 459,2113 554,2113 649,2113 744,2113
  other v3: 1339.76,1078.19 1364.4,1078.19 1385.07,1078.19 1405.74,1078.19 1426.41,1078.19 1447.08,1078.19 1467.75,1078.19 1488.42,1078.19 1509.09,1078.19 1529.75,1078.19 1550.42,1078.19 1571.09,1078.19 1593,1079 1612,1082 1632,1088 1585.71,1091.06 1339.76,1091.82 1364.4,1091.82 1385.07,1091.82 1405.74,1091.82 1426.4,1091.82 1447.07,1091.82 1467.74,1091.82 1488.41,1091.82 1509.08,1091.82 1529.75,1091.82 1550.42,1091.82 1571.09,1091.82 1601.22,1091.57 1619.68,1095.2 1651,1095 1637.28,1101.49 1654.18,1111.08 1692,1128 1340.67,1129.36 1361.34,1129.36 1383.87,1129.36 1402.68,1129.36 1423.35,1129.36 1444.02,1129.36 1464.69,1129.36 1485.36,1129.36 1506.03,1129.36 1526.68,1129.36 1547.33,1129.36 1672.56,1130.04 1340.67,1143 1361.34,1143 1383.87,1143 1402.68,1143 1423.35,1143 1444.02,1143 1464.69,1143 1485.36,1143 1506.03,1143 1526.68,1143 1686.76,1145.04 1594,1146 1611,1153 1627,1169 1733,1172 1639,1186 1704,1189 1649,1206 1757,1208 1780,1251 1639,1410 1631,1424 1664,1426 1651,1453 1642,1465 1630,1478
  other v4: 1708.74,875
  other v5: 498.74,65 498.74,95 1048.43,105 1179.06,105 1204.06,105 1035,125 533.74,130 563.74,130 1058.43,130 1169.06,130 1194.06,130 1433.74,202 1475,205 1518.74,210 1459.94,256.33 957.43,310 1138.43,400 1138.43,425
  other v6: 1747.21,1190.55 998.5,1213.16 1118.1,1405.8 1183.1,1418.17 1123.89,1420.82 1026.18,1439.57 928,1469.47 1026.43,1469.47 1124.86,1469.47 1223.29,1469.47 1420.15,1469.48 1813.85,1469.48 1617,1567.9
  other v7: 1113.74,191.93 543.23,230 604.25,230 1055.67,239 1106,239 1165,240 573.74,260.51 1113.74,308.07
  other v8: 1699,1156
MON_1V: C44.1 C52.1 R68.1 R72.1 R85.2 TP2.1 U5.1 U5.19 U5.20 | length 2128.3
  Top Layer w8: v4(393,1497) 419,1471 419,1455 489,1385 692,1385 727,1420 R72.1@776.97,1420
  L3 w8: v5(390,475) 403,488 722,488 763,529 763,604 739,628 630,628 485,773 485,885 430.46,939.53 430.46,986.53 365,1052 365,1211.29 478,1324.29 478,1393 416.5,1454.5 416.5,1473.5 v4(393,1497)
NetC34_2: C34.2 C35.2 R43.1 U2.8 | length 207.7
  Top Layer w13: U2.8@359,1010.24 359,1041
  Top Layer w16: 359,1041 354.68,1045.31 354.68,1095.31 335,1115 C35.2@335,1143.5 367.13,1143.5 R43.1@390,1166.38
NetC39_2: C39.2 C55.1 R3.1 R81.2 R163.2 R164.2 U5.15 U5.16 U5.17 | length 48.5
  Bottom Layer w15: v2(632,319) 638.7,312.3 R163.2@638.7,273.31
NetC48_2: C48.2 U5.13 | length 89.6
  Top Layer w7: U5.13@638.7,230 661.74,230 v2(674.74,217)
  Bottom Layer w6: v2(674.74,217) 674.74,211.64 C48.2@705,181.38
NetC52_2: C52.2 R85.1 R92.2 U5.3 | length 179.3
  Top Layer w8: R85.1@388.74,226.38 C52.2@438.74,226.38 ; R92.2@438.74,168.62 C52.2@438.74,226.38 ; U5.3@508.78,230 442.36,230 C52.2@438.74,226.38
NetC60_1: C60.1 U9.4 | length 59.5
  Top Layer w15: U9.4@876.14,714.13 880.63,718.62 C60.1@933.74,718.62
NetC61_1: C61.1 U4.8 | length 198.5
  Top Layer w8: v5(1027.74,394) 1027.74,381 1044.84,363.89 U4.8@1044.85,344.49
  Bottom Layer w10: 1023.74,405 1038.74,405 1068.74,435 1068.74,465 1103.74,500 C61.1@1103.74,505
  other v5: 1025.74,418
NetC66_2: C66.2 R167.2 U4.30 | length 343.9
  Top Layer w8: U4.30@1208.23,279.53 1237.27,279.53 v2(1253.74,296)
  Bottom Layer w8: C66.2@1073.62,315 1073.62,298.76 R167.2@1102.38,270 1103.06,270 1133.53,239.53 1133.53,234.27 1148.9,218.9 1177.9,218.9 1191.66,232.66 1191.66,279 1207.78,295.12 1252.86,295.12 v2(1253.74,296)
NetC67_2: C67.2 R166.2 U4.31 | length 549.4
  Top Layer w8: U4.31@1208.23,299.21 1223.64,299.21 1267.47,343.04 1267.47,402.47 v2(1315,450)
  Bottom Layer w6: R166.2@1315,716.38 C67.2@1365,716.38
  Bottom Layer w10: v2(1315,450) 1315,471 1327.8,483.8 1327.8,484.19 1350,506.39 1350,571 1315,606 R166.2@1315,716.38
NetDS1_1: DS1.1 R78.1 | length 99.9
  Top Layer w7.87: DS1.1@353.54,1310 353.54,1316.54 373,1336 408.68,1336 R78.1@430,1314.68
NetDS1_2: DS1.2 Q1.3 | length 61.7
  Top Layer w10: DS1.2@296.46,1310 306,1319.54 Q1.3@306,1367.76
NetJ1_8: J1.8 R17.2 | length 144.8
  Top Layer w6: R17.2@1836.74,346.85 1865.04,346.85 1871.82,353.62 v2(1900.12,353.62)
  Bottom Layer w6: J1.8@1821.54,353.62 v2(1900.12,353.62)
NetJ1_10: J1.10 R15.2 | length 224.9
  Top Layer w6: R15.2@1836.74,386.85 1918.89,386.85 v2(1935.74,370)
  Bottom Layer w6: J1.10@1821.54,373.31 1884.05,373.31 1888.07,377.32 1928.42,377.32 v2(1935.74,370)
NetJ1_11: J1.11 R5.2 | length 186.5
  Bottom Layer w6: R5.2@1461.74,290 1498.74,327.01 1498.74,343.49 1548.24,392.99 J1.11@1595.95,392.99
NetJ1_12: J1.12 R42.2 | length 116.3
  Bottom Layer w6: J1.12@1821.54,392.99 1898.74,392.99 1915.75,410 R42.2@1930.75,410
NetJ1_13: J1.13 R8.1 | length 188.1
  Bottom Layer w6: R8.1@1461.73,325 1476.74,325 1483.74,332 1483.74,345.46 1522.94,384.66 1522.94,401.2 1534.42,412.68 J1.13@1595.95,412.68
NetJ1_14: J1.14 R13.1 | length 122.6
  Bottom Layer w6: J1.14@1821.54,412.68 1898.43,412.68 R13.1@1930.75,445
NetJ1_15: J1.15 R6.1 | length 178
  Bottom Layer w6: R6.1@1461.73,360 1481.31,360 1510.94,389.63 1510.94,413.2 1530.1,432.36 J1.15@1595.95,432.36
NetJ1_16: J1.16 R10.1 | length 137.8
  Top Layer w6: R10.1@1836.74,426.85 1880.59,426.85 v2(1893.74,440)
  Bottom Layer w6: J1.16@1821.54,432.36 1886.1,432.36 v2(1893.74,440)
NetJ1_17: J1.17 R4.1 | length 159.3
  Bottom Layer w6: R4.1@1461.73,395 1461.73,397.56 1482.38,418.2 1497.74,418.2 1531.59,452.05 J1.17@1595.95,452.05
NetJ1_18: J1.18 R31.1 | length 120.8
  Bottom Layer w6: J1.18@1821.54,452.05 1875.79,452.05 1888.74,465 1915.75,465 R31.1@1930.75,480
NetJ1_19: J1.19 R7.2 | length 176.3
  Top Layer w6: R7.2@1587.99,405 1625,405 1660,440 v2(1660,445)
  Bottom Layer w6: J1.19@1595.95,471.73 1649.7,471.73 1660,461.43 v2(1660,445)
NetJ1_21: J1.21 R9.2 | length 164.9
  Bottom Layer w6: R9.2@1461.74,430 1477.21,430 1477.4,430.2 1492.77,430.2 1526.61,464.05 1526.61,473.05 1544.98,491.42 J1.21@1595.95,491.42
